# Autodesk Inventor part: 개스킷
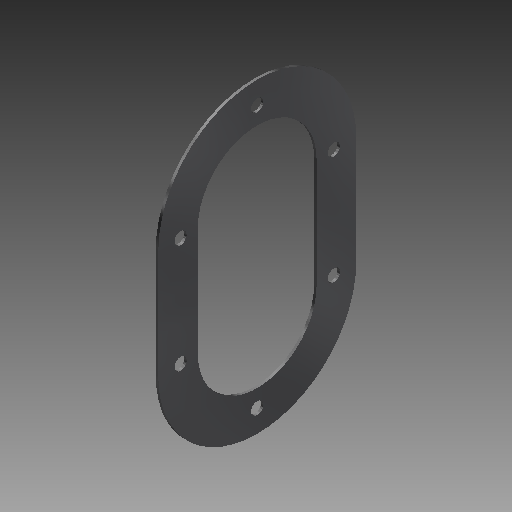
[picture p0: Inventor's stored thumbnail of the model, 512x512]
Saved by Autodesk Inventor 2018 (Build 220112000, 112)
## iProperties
Created: 2019-03
Part Number: 개스킷
Material: 고무
Document SubType Name: Modeling
Designer: mduedu
Density: 1 g/cm^3
Appearance: 고무 - 검은색 - 버전 1.1
Author: mduedu
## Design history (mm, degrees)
sketch "스케치1"
  geometry: L1 (-62, 40)-(62, 40); L2 (62, 40)-(62, -40); L3 (62, -40)-(-62, -40); L4 (-62, -40)-(-62, 40); L5 (-62, 40)-(62, -40); L6 (62, 40)-(-62, -40); 1 further point
  constraints: 12 end point, 2 midpoint, 2 parallel, 1 horizontal, 1 perpendicular
  dimensions: "d21" = 124 distance of L2.end L3.end; "d22" = 80 distance of L1.end L2.end
extrude "돌출1" new body sketch "스케치1" distance "d3" = 1; taper "d4" = 0 deg
fillet "모깎기2"
fillet "모깎기3"
sketch "스케치2" dims "d6" = 48
  geometry: L1 (-24, -22)-(24, -22); L2 (24, -22)-(24, 22); L3 (24, 22)-(-24, 22); L4 (-24, 22)-(-24, -22); L5 (-24, -22)-(24, 22); L6 (24, -22)-(-24, 22); 3 further points
  constraints: 12 end point, 4 midpoint, 2 horizontal alignment, 2 parallel, 1 horizontal, 1 perpendicular, 4 other
  dimensions: "d8" = 22 distance from line of L3 point (0, 0)
extrude "돌출2" cut sketch "스케치2" extent not by distance; stored distance "d9" = 1; taper "d10" = 0 deg
sketch "스케치3"
  geometry: L1 (24, -22)-(24, 22) reference; L2 (-24, 22)-(-24, -22) reference; L3 (31, 22)-(31, -22); L4 (-31, -22)-(-31, 22); A1 r 24 centre (0, 22) between (24, 22) and (-24, 22) reference; A2 r 24 centre (0, -22) between (-24, -22) and (24, -22) reference; A3 r 31 centre (0, 22) between (31, 22) and (-31, 22); A4 r 31 centre (0, -22) between (-31, -22) and (31, -22); 7 further points
  constraints: 6 point on circle, 4 coincident, 4 end point, 2 centre point, 3 other
  dimensions: "d26" = 62 distance between parallel lines of L3 L4; "d28" = 7 distance between parallel lines of L4 L2 (derived); "d29" = 48 distance between parallel lines of L1 L2 (derived); "d30" = 31 radius of A3 (derived)
hole "구멍1" sketch "스케치3" at (0, 53), (31, 22), (31, -22), (0, -53), (-31, -22), (-31, 22) diameter "d14" = 5; stored, may be unused: countersink angle "d18" = 90 deg, drill point angle "d20" = 118 deg; dims "d15" = 6, "d16" = 4, "d17" = 2, "d19" = 8
node "솔리드1"
